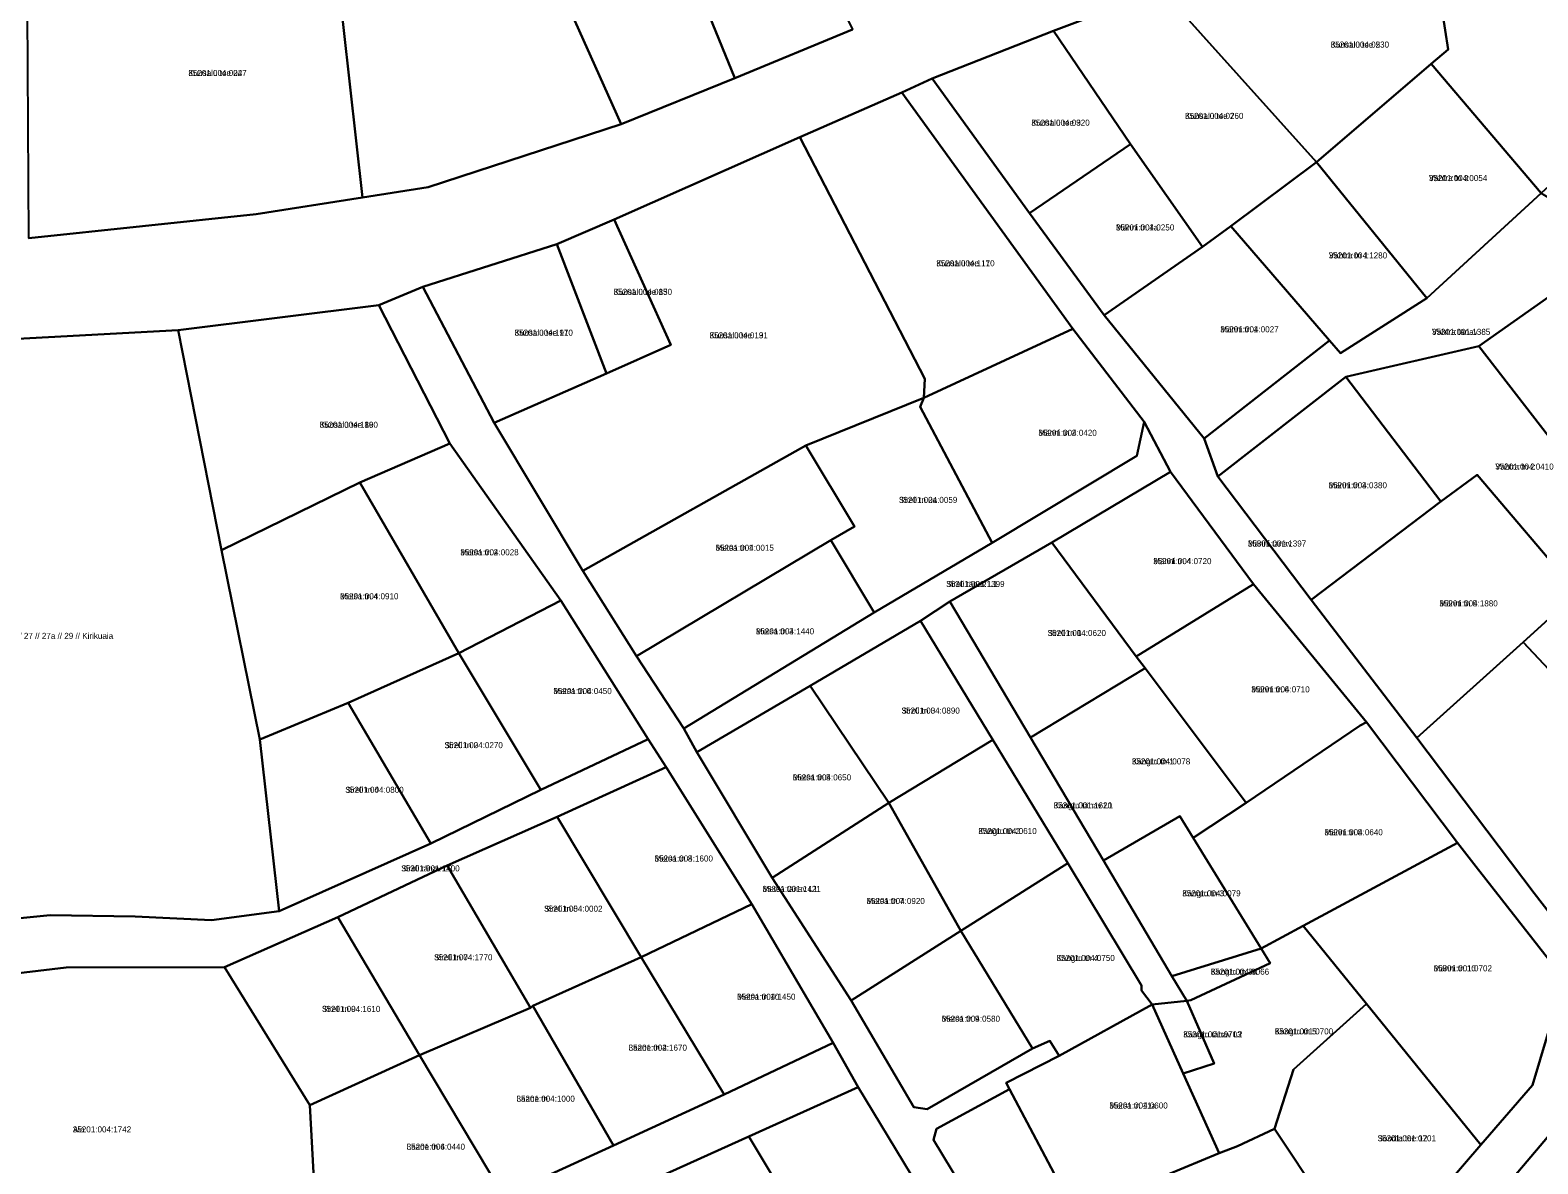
# Model space of a CAD drawing. Extents: x 570181 to 611446, y 6571894 to 6617855.
# Drawn here: x 581585 to 581959.8, y 6590403.2 to 6590685 of the extents above; entities that cross this region are included whole.
import ezdxf

# ---------------------------------------------------------------- set-up
doc = ezdxf.new("R2010")
doc.units = 0
for name, color, linetype in [('L_AADRESS', 7, 'Continuous'), ('PIIR', 7, 'Continuous'), ('TUNNUS', 7, 'Continuous')]:
    doc.layers.add(name, color=color, linetype=linetype)

msp = doc.modelspace()

# ---------------------------------------------------------------- linework, layer by layer
at = {"layer": 'PIIR'}
for points in [[(581760.16, 6590673.03), (581729.26, 6590748.76), (581753.11, 6590759.48), (581789.43, 6590685.1)], [(581760.16, 6590673.03), (581731.95, 6590661.58), (581698.13, 6590737.03), (581729.26, 6590748.76)], [(581698.13, 6590737.03), (581731.95, 6590661.58), (581683.93, 6590645.93), (581667.62, 6590643.36), (581659.76, 6590713.91), (581669.61, 6590717.7), (581685.4, 6590726.53), (581685.57, 6590730.62)], [(581667.62, 6590643.36), (581641.22, 6590639.2), (581584.68, 6590633.25), (581584.28, 6590703.78), (581593.74, 6590704.77), (581642.22, 6590707.47), (581659.76, 6590713.91)], [(581866.34, 6590694.99), (581889.15, 6590701.67), (581908.81, 6590706.05), (581917.82, 6590707.2), (581933.08, 6590709.1), (581937.49, 6590680.18), (581933.3, 6590676.59), (581904.83, 6590652.16)], [(581933.08, 6590709.1), (581953.07, 6590706.47), (581963.87, 6590702.4), (582009.43, 6590688.82), (581960.66, 6590644.48), (581933.3, 6590676.59), (581937.49, 6590680.18)], [(581839.42, 6590684.82), (581866.34, 6590694.99), (581904.83, 6590652.16), (581883.48, 6590636.27), (581876.41, 6590631.15), (581858.54, 6590656.65)], [(581833.48, 6590639.52), (581809.27, 6590672.92), (581839.42, 6590684.82), (581858.54, 6590656.65)], [(581904.83, 6590652.16), (581933.3, 6590676.59), (581960.66, 6590644.48), (581932.23, 6590618.32)], [(581801.68, 6590669.44), (581809.27, 6590672.92), (581833.48, 6590639.52), (581852.03, 6590614.14), (581876.85, 6590583.47), (581880.24, 6590574), (581903.5, 6590543.39), (581929.73, 6590509.06), (581958.93, 6590470.53), (581962.85, 6590465.36), (581973.77, 6590461.13), (581966.37, 6590449.16), (581944.45, 6590477.05), (581939.86, 6590482.99), (581917.25, 6590513.01), (581889.11, 6590547.25), (581868.5, 6590575.21), (581861.99, 6590587.65), (581844.18, 6590610.72)], [(581776.36, 6590658.4), (581801.68, 6590669.44), (581844.18, 6590610.72), (581807.21, 6590593.6), (581807.45, 6590598.33)], [(581776.36, 6590658.4), (581807.45, 6590598.33), (581807.21, 6590593.6), (581777.82, 6590581.74), (581722.43, 6590550.63), (581700.37, 6590587.38), (581728.27, 6590599.67), (581744.26, 6590606.8), (581730.23, 6590637.94)], [(581852.03, 6590614.14), (581833.48, 6590639.52), (581858.54, 6590656.65), (581876.41, 6590631.15)], [(581932.23, 6590618.32), (581910.72, 6590604.72), (581908.01, 6590607.86), (581883.48, 6590636.27), (581904.83, 6590652.16)], [(581932.23, 6590618.32), (581960.66, 6590644.48), (581981.37, 6590631.98), (581945.11, 6590606.42), (581912.08, 6590598.84), (581880.24, 6590574), (581876.85, 6590583.47), (581908.01, 6590607.86), (581910.72, 6590604.72)], [(581730.23, 6590637.94), (581744.26, 6590606.8), (581728.27, 6590599.67), (581715.91, 6590631.8)], [(581883.48, 6590636.27), (581908.01, 6590607.86), (581876.85, 6590583.47), (581852.03, 6590614.14), (581876.41, 6590631.15)], [(581715.91, 6590631.8), (581728.27, 6590599.67), (581700.37, 6590587.38), (581682.61, 6590621.19)], [(581983.17, 6590557.31), (581945.11, 6590606.42), (581981.37, 6590631.98), (582003.29, 6590603.84), (581983.17, 6590600.72), (581997.87, 6590582.77), (582004.47, 6590574.92)], [(581671.66, 6590616.59), (581689.36, 6590582.24), (581666.98, 6590572.51), (581632.59, 6590555.7), (581621.82, 6590610.38)], [(581473, 6590597), (581522, 6590605), (581621.82, 6590610.38), (581632.59, 6590555.7), (581642.11, 6590508.72), (581646.92, 6590466.03), (581630.08, 6590463.79), (581611.15, 6590464.68), (581590, 6590465), (581510, 6590457), (581494, 6590485), (581486, 6590523), (581455, 6590587)], [(581807.21, 6590593.6), (581844.18, 6590610.72), (581861.99, 6590587.65), (581860.13, 6590579.2), (581824.19, 6590557.58), (581806.29, 6590591.36)], [(581944.72, 6590574.46), (581935.66, 6590567.84), (581912.08, 6590598.84), (581945.11, 6590606.42), (581983.17, 6590557.31), (581969.65, 6590545.1)], [(581903.5, 6590543.39), (581880.24, 6590574), (581912.08, 6590598.84), (581935.66, 6590567.84)], [(581777.82, 6590581.74), (581807.21, 6590593.6), (581806.29, 6590591.36), (581824.19, 6590557.58), (581794.86, 6590540.23), (581784.07, 6590558.25), (581789.92, 6590561.58)], [(581794.86, 6590540.23), (581824.19, 6590557.58), (581860.13, 6590579.2), (581861.99, 6590587.65), (581868.5, 6590575.21), (581838.98, 6590557.64), (581813.68, 6590543), (581806.36, 6590538.21), (581778.96, 6590521.98), (581750.73, 6590505.53), (581747.54, 6590511.4)], [(581689.36, 6590582.24), (581716.94, 6590543.25), (581691.57, 6590530.16), (581666.98, 6590572.51)], [(581789.92, 6590561.58), (581784.07, 6590558.25), (581735.76, 6590529.39), (581722.43, 6590550.63), (581777.82, 6590581.74)], [(581859.94, 6590529.3), (581838.98, 6590557.64), (581868.5, 6590575.21), (581889.11, 6590547.25)], [(581969.65, 6590545.1), (581983.17, 6590557.31), (582004.47, 6590574.92), (582033.77, 6590536.2), (582016.43, 6590509.32), (581994.99, 6590534.99), (581972.9, 6590515.1), (581956.15, 6590532.9)], [(581666.98, 6590572.51), (581691.57, 6590530.16), (581664.09, 6590517.77), (581642.11, 6590508.72), (581632.59, 6590555.7)], [(581929.73, 6590509.06), (581903.5, 6590543.39), (581935.66, 6590567.84), (581944.72, 6590574.46), (581969.65, 6590545.1), (581956.15, 6590532.9)], [(581735.76, 6590529.39), (581784.07, 6590558.25), (581794.86, 6590540.23), (581747.54, 6590511.4)], [(581833.68, 6590509.2), (581813.68, 6590543), (581838.98, 6590557.64), (581859.94, 6590529.3), (581862.23, 6590526.39)], [(581887.3, 6590492.96), (581862.23, 6590526.39), (581859.94, 6590529.3), (581889.11, 6590547.25), (581917.25, 6590513.01), (581915.66, 6590512.17)], [(581691.57, 6590530.16), (581716.94, 6590543.25), (581738.63, 6590508.79), (581711.96, 6590496.15)], [(581806.36, 6590538.21), (581813.68, 6590543), (581833.68, 6590509.2), (581851.84, 6590478.58), (581868.84, 6590449.91), (581872.57, 6590443.71), (581863.97, 6590442.79), (581861.3, 6590446.3), (581861.3, 6590447.52), (581842.96, 6590477.93), (581824.3, 6590508.62)], [(581798.5, 6590492.92), (581778.96, 6590521.98), (581806.36, 6590538.21), (581824.3, 6590508.62)], [(581684.66, 6590482.87), (581664.09, 6590517.77), (581691.57, 6590530.16), (581711.96, 6590496.15)], [(581929.73, 6590509.06), (581956.15, 6590532.9), (581972.9, 6590515.1), (581990.65, 6590496.12), (581997.47, 6590488.87), (581973.77, 6590461.13), (581962.85, 6590465.36), (581958.93, 6590470.53)], [(581833.68, 6590509.2), (581862.23, 6590526.39), (581887.3, 6590492.96), (581874.16, 6590484.26), (581870.84, 6590489.66), (581851.84, 6590478.58)], [(581769.5, 6590474.3), (581750.73, 6590505.53), (581778.96, 6590521.98), (581798.5, 6590492.92)], [(581646.92, 6590466.03), (581642.11, 6590508.72), (581664.09, 6590517.77), (581684.66, 6590482.87)], [(581901.45, 6590462.37), (581891.02, 6590456.77), (581874.16, 6590484.26), (581887.3, 6590492.96), (581915.66, 6590512.17), (581917.25, 6590513.01), (581939.86, 6590482.99)], [(581510, 6590457), (581590, 6590465), (581611.15, 6590464.68), (581630.08, 6590463.79), (581646.92, 6590466.03), (581684.66, 6590482.87), (581711.96, 6590496.15), (581738.63, 6590508.79), (581743.16, 6590501.84), (581716.06, 6590489.5), (581688.71, 6590477.38), (581661.52, 6590464.57), (581633.32, 6590452.09), (581594, 6590452), (581518, 6590443)], [(581816.35, 6590461.16), (581798.5, 6590492.92), (581824.3, 6590508.62), (581842.96, 6590477.93)], [(581743.16, 6590501.84), (581764.43, 6590467.8), (581736.9, 6590454.61), (581716.06, 6590489.5)], [(581789.09, 6590443.85), (581769.5, 6590474.3), (581798.5, 6590492.92), (581816.35, 6590461.16)], [(581688.71, 6590477.38), (581716.06, 6590489.5), (581736.9, 6590454.61), (581710, 6590442.46), (581709.38, 6590442.01)], [(581851.84, 6590478.58), (581870.84, 6590489.66), (581874.16, 6590484.26), (581891.02, 6590456.77), (581868.84, 6590449.91)], [(581901.45, 6590462.37), (581939.86, 6590482.99), (581944.45, 6590477.05), (581966.37, 6590449.16), (581958.47, 6590422.78), (581945.64, 6590407.92), (581917.2, 6590442.96)], [(581688.71, 6590477.38), (581709.38, 6590442.01), (581681.82, 6590430.23), (581661.52, 6590464.57)], [(581834.16, 6590431.93), (581816.35, 6590461.16), (581842.96, 6590477.93), (581861.3, 6590447.52), (581861.3, 6590446.3), (581863.97, 6590442.79), (581840.84, 6590430.05), (581838.47, 6590433.81)], [(581736.9, 6590454.61), (581764.43, 6590467.8), (581784.65, 6590433.34), (581757.57, 6590420.44)], [(581681.82, 6590430.23), (581654.58, 6590417.8), (581633.32, 6590452.09), (581661.52, 6590464.57)], [(581879.34, 6590428.2), (581872.57, 6590443.71), (581873.52, 6590443.88), (581893.31, 6590453.12), (581891.02, 6590456.77), (581901.45, 6590462.37), (581917.2, 6590442.96), (581899.08, 6590426.71), (581894.34, 6590411.91), (581885.16, 6590407.6), (581880.58, 6590405.87), (581871.66, 6590425.7)], [(581804.72, 6590417.34), (581789.09, 6590443.85), (581816.35, 6590461.16), (581834.16, 6590431.93), (581808.01, 6590416.83)], [(581710, 6590442.46), (581736.9, 6590454.61), (581757.57, 6590420.44), (581730.03, 6590407.79)], [(581868.84, 6590449.91), (581891.02, 6590456.77), (581893.31, 6590453.12), (581873.52, 6590443.88), (581872.57, 6590443.71)], [(581633.32, 6590452.09), (581654.58, 6590417.8), (581656.86, 6590375.09), (581630, 6590370), (581579, 6590376), (581549, 6590389), (581518, 6590443), (581594, 6590452)], [(581871.66, 6590425.7), (581863.97, 6590442.79), (581872.57, 6590443.71), (581879.34, 6590428.2)], [(581681.82, 6590430.23), (581709.38, 6590442.01), (581710, 6590442.46), (581730.03, 6590407.79), (581702.66, 6590395.32)], [(581827.64, 6590423.36), (581840.84, 6590430.05), (581863.97, 6590442.79), (581871.66, 6590425.7), (581880.58, 6590405.87), (581863.02, 6590398.63), (581844.73, 6590391.16), (581828.48, 6590421.77)], [(581917.2, 6590442.96), (581945.64, 6590407.92), (581918.18, 6590376.04), (581894.34, 6590411.91), (581899.08, 6590426.71)], [(581549, 6590389), (581579, 6590376), (581630, 6590370), (581656.86, 6590375.09), (581702.66, 6590395.32), (581730.03, 6590407.79), (581757.57, 6590420.44), (581784.65, 6590433.34), (581790.85, 6590422.29), (581763.66, 6590410.02), (581736.3, 6590397.65), (581690.71, 6590377.01), (581666.55, 6590367.91), (581633.02, 6590354.98), (581592.97, 6590356.98), (581580.01, 6590345.03)], [(581656.86, 6590375.09), (581654.58, 6590417.8), (581681.82, 6590430.23), (581702.66, 6590395.32)], [(581942.83, 6590386.98), (581978.89, 6590429.48), (582001.33, 6590389.72), (581962.79, 6590366.54), (581959.49, 6590370.02)], [(581763.66, 6590410.02), (581790.85, 6590422.29), (581811.56, 6590388.1), (581784.25, 6590375.8)], [(581832.59, 6590371.07), (581809.61, 6590409.22), (581810.29, 6590411.89), (581828.48, 6590421.77), (581844.73, 6590391.16), (581863.02, 6590398.63), (581867.53, 6590391.51)], [(581763.66, 6590410.02), (581784.25, 6590375.8), (581756.8, 6590363.18), (581736.3, 6590397.65)], [(581882.47, 6590365.57), (581867.53, 6590391.51), (581863.02, 6590398.63), (581880.58, 6590405.87), (581885.16, 6590407.6), (581894.34, 6590411.91), (581918.18, 6590376.04), (581910.1, 6590366.26), (581893.92, 6590347.12)]]:
    msp.add_lwpolyline(points, close=True, dxfattribs=at)
for points in [[(581866.34, 6590694.99), (581839.42, 6590684.82), (581809.27, 6590672.92), (581801.68, 6590669.44), (581776.36, 6590658.4), (581730.23, 6590637.94), (581715.91, 6590631.8), (581682.61, 6590621.19), (581671.66, 6590616.59), (581621.82, 6590610.38), (581522, 6590605)], [(581584.68, 6590633.25), (581641.22, 6590639.2), (581667.62, 6590643.36), (581683.93, 6590645.93), (581731.95, 6590661.58), (581760.16, 6590673.03), (581789.43, 6590685.1)], [(581811.56, 6590388.1), (581790.85, 6590422.29), (581784.65, 6590433.34), (581764.43, 6590467.8), (581743.16, 6590501.84), (581738.63, 6590508.79), (581716.94, 6590543.25), (581689.36, 6590582.24), (581671.66, 6590616.59), (581682.61, 6590621.19), (581700.37, 6590587.38), (581722.43, 6590550.63), (581735.76, 6590529.39), (581747.54, 6590511.4), (581750.73, 6590505.53), (581769.5, 6590474.3), (581789.09, 6590443.85), (581804.72, 6590417.34), (581808.01, 6590416.83), (581834.16, 6590431.93), (581838.47, 6590433.81), (581840.84, 6590430.05), (581827.64, 6590423.36), (581828.48, 6590421.77), (581810.29, 6590411.89), (581809.61, 6590409.22), (581832.59, 6590371.07)], [(581918.18, 6590376.04), (581945.64, 6590407.92), (581958.47, 6590422.78), (581966.37, 6590449.16)], [(581978.89, 6590429.48), (581942.83, 6590386.98)]]:
    msp.add_lwpolyline(points, dxfattribs=at)

# ---------------------------------------------------------------- texts
at = {"layer": 'L_AADRESS'}
for s, p in [('Kuusalu tee 5', (581908.33, 6590680.63)), ('Kuusalu tee 22', (581624.35, 6590673.58)), ('Kuusalu tee 7', (581872.12, 6590662.91)), ('Kuusalu tee 9', (581833.91, 6590661.23)), ('Vahtra tn 3', (581932.74, 6590647.45)), ('Männi tn 1a', (581854.94, 6590635.18)), ('Kuusalu tee 11', (581810.27, 6590626.29)), ('Vahtra tn 1', (581907.85, 6590628.23)), ('Kuusalu tee 15', (581730.08, 6590619.18)), ('Kuusalu tee 17', (581705.44, 6590609.04)), ('Kuusalu tee 13', (581753.91, 6590608.38)), ('Männi tn 1', (581880.88, 6590609.87)), ('Vahtra tänav', (581933.49, 6590609.24)), ('Kuusalu tee 19', (581656.97, 6590586.15)), ('Männi tn 2', (581835.67, 6590584.15)), ('Vahtra tn 2', (581949.25, 6590575.76)), ('Männi tn 3', (581907.8, 6590571.12)), ('Sireli tn 2a', (581801, 6590567.48)), ('Metsa tn 2', (581691.96, 6590554.46)), ('Metsa tn 1', (581755.4, 6590555.57)), ('Männi tänav', (581887.73, 6590556.64)), ('Männi tn 4', (581864.19, 6590552.26)), ('Metsa tn 4', (581662.08, 6590543.53)), ('Sireli tänav L1', (581812.75, 6590546.59)), ('Männi tn 5', (581935.35, 6590541.76)), ('Kuusalu tee 21 // 23 // 25 // 27 // 27a // 29 // Kirikuaia', (581558.94, 6590533.69)), ('Metsa tn 3', (581765.42, 6590534.82)), ('Sireli tn 1', (581837.95, 6590534.41)), ('Metsa tn 6', (581715.1, 6590519.97)), ('Männi tn 6', (581888.59, 6590520.39)), ('Sireli tn 3', (581801.63, 6590515.12)), ('Sireli tn 2', (581688.03, 6590506.53)), ('Kangru tn 1', (581858.91, 6590502.49)), ('Metsa tn 5', (581774.61, 6590498.52)), ('Sireli tn 4', (581663.38, 6590495.43)), ('Kangru tänav L1', (581839.46, 6590491.56)), ('Kangru tn 2', (581820.73, 6590485.18)), ('Männi tn 8', (581906.77, 6590484.89)), ('Sireli tänav L2', (581677.29, 6590475.9)), ('Metsa tn 8', (581740.25, 6590478.36)), ('Metsa tänav L1', (581767.08, 6590470.81)), ('Kangru tn 3', (581871.43, 6590469.71)), ('Sireli tn 5', (581712.8, 6590465.89)), ('Metsa tn 7', (581792.93, 6590467.81)), ('Sireli tn 7', (581685.45, 6590453.81)), ('Kangru tn 4', (581840.16, 6590453.65)), ('Kangru tn 3a', (581878.52, 6590450.24)), ('Männi tn 10', (581933.91, 6590451.08)), ('Metsa tn 10', (581760.77, 6590444.01)), ('Sireli tn 9', (581657.57, 6590440.99)), ('Metsa tn 9', (581811.62, 6590438.54)), ('Kangru tänav L2', (581871.66, 6590434.66)), ('Kangru tn 5', (581894.43, 6590435.4)), ('Laane tn 2', (581733.79, 6590431.36)), ('Laane tn 4', (581705.93, 6590418.67)), ('Metsa tn 11a', (581853.31, 6590416.98)), ('Aia', (581595.64, 6590411.04)), ('Soodla tee 12', (581919.99, 6590408.83)), ('Laane tn 6', (581678.62, 6590406.74))]:
    msp.add_text(s, height=1.5, dxfattribs=at).set_placement(p)
at = {"layer": 'TUNNUS'}
for s, p in [('35201:004:0230', (581908.33, 6590680.63)), ('35201:004:0047', (581624.35, 6590673.58)), ('35201:004:0260', (581872.12, 6590662.91)), ('35201:004:0320', (581833.91, 6590661.23)), ('35201:004:0054', (581932.74, 6590647.45)), ('35201:004:0250', (581854.94, 6590635.18)), ('35201:004:1170', (581810.27, 6590626.29)), ('35201:004:1280', (581907.85, 6590628.23)), ('35201:004:0830', (581730.08, 6590619.18)), ('35201:004:1910', (581705.44, 6590609.04)), ('35201:004:0191', (581753.91, 6590608.38)), ('35201:004:0027', (581880.88, 6590609.87)), ('35301:001:1385', (581933.49, 6590609.24)), ('35201:004:1860', (581656.97, 6590586.15)), ('35201:004:0420', (581835.67, 6590584.15)), ('35201:004:0410', (581949.25, 6590575.76)), ('35201:004:0380', (581907.8, 6590571.12)), ('35201:004:0059', (581801, 6590567.48)), ('35201:004:0028', (581691.96, 6590554.46)), ('35201:004:0015', (581755.4, 6590555.57)), ('35301:001:1397', (581887.73, 6590556.64)), ('35201:004:0720', (581864.19, 6590552.26)), ('35201:004:0910', (581662.08, 6590543.53)), ('35301:001:1399', (581812.75, 6590546.59)), ('35201:004:1880', (581935.35, 6590541.76)), ('35201:004:1440', (581765.42, 6590534.82)), ('35201:004:0620', (581837.95, 6590534.41)), ('35201:004:0450', (581715.1, 6590519.97)), ('35201:004:0710', (581888.59, 6590520.39)), ('35201:004:0890', (581801.63, 6590515.12)), ('35201:004:0270', (581688.03, 6590506.53)), ('35201:004:0078', (581858.91, 6590502.49)), ('35201:004:0650', (581774.61, 6590498.52)), ('35201:004:0800', (581663.38, 6590495.43)), ('35301:001:1620', (581839.46, 6590491.56)), ('35201:004:0610', (581820.73, 6590485.18)), ('35201:004:0640', (581906.77, 6590484.89)), ('35301:001:1400', (581677.29, 6590475.9)), ('35201:004:1600', (581740.25, 6590478.36)), ('35301:001:1421', (581767.08, 6590470.81)), ('35201:004:0079', (581871.43, 6590469.71)), ('35201:004:0002', (581712.8, 6590465.89)), ('35201:004:0920', (581792.93, 6590467.81)), ('35201:004:1770', (581685.45, 6590453.81)), ('35201:004:0750', (581840.16, 6590453.65)), ('35201:004:0066', (581878.52, 6590450.24)), ('35301:001:0702', (581933.91, 6590451.08)), ('35201:004:1450', (581760.77, 6590444.01)), ('35201:004:1610', (581657.57, 6590440.99)), ('35201:004:0580', (581811.62, 6590438.54)), ('35301:001:0703', (581871.66, 6590434.66)), ('35301:001:0700', (581894.43, 6590435.4)), ('35201:004:1670', (581733.79, 6590431.36)), ('35201:004:1000', (581705.93, 6590418.67)), ('35201:004:0600', (581853.31, 6590416.98)), ('35201:004:1742', (581595.64, 6590411.04)), ('35301:001:0701', (581919.99, 6590408.83)), ('35201:004:0440', (581678.62, 6590406.74))]:
    msp.add_text(s, height=1.5, dxfattribs=at).set_placement(p)

doc.saveas('drawing.dxf')
